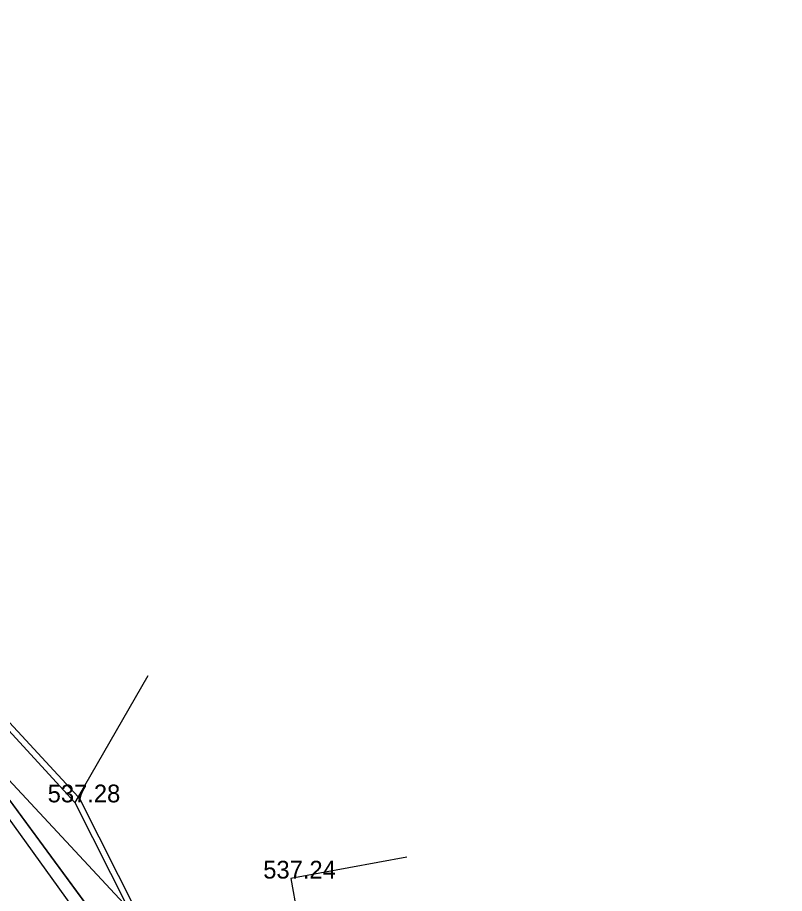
# Model space of a CAD drawing. Extents: x -669393 to -668650, y -1126925 to -1126294.
# Drawn here: x -669046.62 to -669014.21, y -1126707.26 to -1126670.25 of the extents above; entities that cross this region are included whole.
import ezdxf

# ---------------------------------------------------------------- set-up
doc = ezdxf.new("R2010")
doc.units = 0
for name, color, linetype in [('G_Bod_tecka', 7, 'Continuous'), ('G_Bod_vyska', 7, 'Continuous'), ('G_Breh_Teren', 7, 'Continuous'), ('G_Budovy_Objekty', 7, 'Continuous'), ('G_Ploty', 7, 'Continuous'), ('G_Z_ELsilove_podz_kotovane', 7, 'Continuous'), ('G_Z_SPOJE_podz_geodeticky', 7, 'Continuous'), ('G_Z_SPOJE_podz_kotovane', 7, 'Continuous'), ('G_Z_SPOJE_podz_priblizne', 7, 'Continuous'), ('Vrstva 62', 7, 'Continuous')]:
    doc.layers.add(name, color=color, linetype=linetype)

msp = doc.modelspace()

# ---------------------------------------------------------------- linework, layer by layer
at = {"layer": 'G_Bod_tecka'}
for p, q in [((-669044.19, -1126703.41), (-669044.19, -1126703.41)), ((-669035.07, -1126706.63), (-669035.07, -1126706.63))]:
    msp.add_line(p, q, dxfattribs=at)
at = {"layer": 'G_Breh_Teren'}
msp.add_lwpolyline([(-669041.94, -1126707.88), (-669051.51, -1126697.61)], dxfattribs=at)
at = {"layer": 'G_Budovy_Objekty'}
for p, q in [((-669030.16, -1126705.72), (-669035.07, -1126706.63)), ((-669035.07, -1126706.63), (-669033.02, -1126717.76))]:
    msp.add_line(p, q, dxfattribs=at)
at = {"layer": 'G_Ploty'}
for p, q in [((-669051.5, -1126695.49), (-669044.19, -1126703.41)), ((-669044.06, -1126703.18), (-669051.28, -1126695.36)), ((-669041.11, -1126698.06), (-669044.06, -1126703.18)), ((-669044.06, -1126703.18), (-669044.19, -1126703.41)), ((-669043.98, -1126703.26), (-669044.06, -1126703.18)), ((-669036.31, -1126718.5), (-669043.98, -1126703.26)), ((-669044.19, -1126703.41), (-669041.94, -1126707.88))]:
    msp.add_line(p, q, dxfattribs=at)
at = {"layer": 'G_Z_ELsilove_podz_kotovane'}
msp.add_lwpolyline([(-668991.15, -1126787.71), (-668992.47, -1126784.68), (-668992.94, -1126784.14), (-668993.85, -1126784), (-668994.99, -1126783.88), (-668997.24, -1126783.28), (-668999.66, -1126783.12), (-669000.56, -1126782.76), (-669001.95, -1126780.63), (-669003.7, -1126777.68), (-669006.31, -1126773.26), (-669007.38, -1126772.1), (-669009.06, -1126769.68), (-669009.55, -1126768.64), (-669025.04, -1126740.9), (-669039.34, -1126713.66), (-669057.59, -1126688.86), (-669057.53, -1126686.66), (-669073.8, -1126662.04), (-669088.6, -1126634.97), (-669111.98, -1126614.96), (-669163.86, -1126582.84), (-669189.05, -1126566.12), (-669226.41, -1126541.64)], dxfattribs=at)
at = {"layer": 'G_Z_SPOJE_podz_geodeticky'}
msp.add_lwpolyline([(-669042.14, -1126711.66), (-669042.16, -1126710.8), (-669048.67, -1126701.76), (-669050.99, -1126698.94), (-669051.74, -1126696.72), (-669052.32, -1126693.14), (-669051.84, -1126691.33), (-669051.61, -1126689.78), (-669050.9, -1126687.48), (-669053.66, -1126675.09), (-669050.45, -1126667.76), (-669048.85, -1126659.26)], dxfattribs=at)
at = {"layer": 'G_Z_SPOJE_podz_kotovane'}
msp.add_lwpolyline([(-669042.14, -1126711.66), (-669042.16, -1126710.8), (-669048.67, -1126701.76), (-669050.99, -1126698.94), (-669051.74, -1126696.72), (-669052.32, -1126693.14), (-669051.84, -1126691.33), (-669051.61, -1126689.78), (-669050.9, -1126687.48), (-669053.66, -1126675.09), (-669050.45, -1126667.76), (-669048.85, -1126659.26)], dxfattribs=at)
at = {"layer": 'G_Z_SPOJE_podz_priblizne'}
msp.add_lwpolyline([(-669042.14, -1126711.66), (-669042.16, -1126710.8), (-669048.67, -1126701.76), (-669050.99, -1126698.94), (-669051.74, -1126696.72), (-669052.32, -1126693.14), (-669051.84, -1126691.33), (-669051.61, -1126689.78), (-669050.9, -1126687.48), (-669053.66, -1126675.09), (-669050.45, -1126667.76), (-669048.85, -1126659.26)], dxfattribs=at)
at = {"layer": 'Vrstva 62'}
msp.add_line((-669039.34, -1126713.66), (-669057.59, -1126688.86), dxfattribs=at)

# ---------------------------------------------------------------- texts
at = {"layer": 'G_Bod_vyska'}
for s, p in [('537.28', (-669045.344, -1126703.41)), ('537.24', (-669036.234, -1126706.63))]:
    msp.add_text(s, height=0.75, dxfattribs=at).set_placement(p)

doc.saveas('drawing.dxf')
